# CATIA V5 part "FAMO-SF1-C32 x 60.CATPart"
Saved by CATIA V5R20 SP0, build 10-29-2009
Part number: FAMO-SF1-C32 x 60
Definition: NONE
Nomenclature: FAMO-SF1-C32 x 60
Source: Unknown
Description: FAMO-SF1-C32 x 60
Bounding box of the stored display mesh (mm): x -34 to 26, y -26.5 to 26.5, z -26.5 to 26.5
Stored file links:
  C:\Users\Utente\Desktop\IO LAVORO\3D X SITO CF\X SITO\FAMO\FAMO-SF1-C32 x 60.CATPart
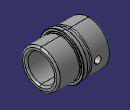
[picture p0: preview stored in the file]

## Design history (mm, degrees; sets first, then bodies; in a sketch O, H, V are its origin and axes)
Body1 "FAMO-SF1-C32 x 60" (main body)
  Solid1: solid without history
